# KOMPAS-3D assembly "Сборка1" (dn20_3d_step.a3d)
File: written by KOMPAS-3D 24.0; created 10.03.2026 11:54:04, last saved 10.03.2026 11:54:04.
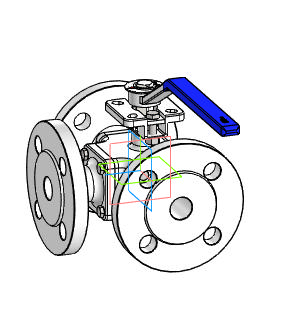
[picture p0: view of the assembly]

Document properties: Автор: R2D2; Полное имя файла: E:\Работа\Зайцев\BV3232P(4pc)-FP-3WL-F-ISO-H Кран шаровой DN.ru Ду15-100 Ру16\DN20\исходные материалы\dn20_3d_step.a3d

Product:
- Component [detail]: Деталь  | qty 1  | Автор: R2D2; source file: Деталь Деталь.m3d
- Component [detail]: Деталь1  | qty 1  | Автор: R2D2; source file: Деталь1 Деталь1.m3d
- Component [detail]: AS 1110 - M6 x 20  | qty 1  | Автор: R2D2; source file: AS 1110 - M6 x 20 AS 1110 - M6 x 20.m3d
- Component [detail]: AS 1110 - M6 x 20  | qty 1  | Комментарий: Болты и винты   шестигранные точные   метрические ISO; Автор: R2D2; additional columns: Сталь, мягкая; source file: AS 1110 - M6 x 20 AS 1110 - M6 x 20.m3d
- Component [detail]: ANSI B18.2.4.2M - M6x1 - 10  | designation ANSI B18.2.4.2M - M6x1  | qty 1  | Автор: R2D2; source file: ANSI B18.2.4.2M - M6x1 ANSI B18.2.4.2M - M6x1 - 10.m3d
- Component [detail]: ANSI B18.2.4.2M - M6x1 - 10  | designation ANSI B18.2.4.2M - M6x1  | qty 1  | Комментарий: Типы метрических   шестигранных гаек   2; Автор: R2D2; additional columns: Сталь, мягкая; source file: ANSI B18.2.4.2M - M6x1 ANSI B18.2.4.2M - M6x1 - 10.m3d
- Component [detail]: AS 1110 - M5 x 10  | qty 1  | Автор: R2D2; source file: AS 1110 - M5 x 10 AS 1110 - M5 x 10.m3d
- Component [detail]: AS 1110 - M5 x 10  | qty 11  | Комментарий: Болты и винты   шестигранные точные   метрические ISO; Автор: R2D2; additional columns: Сталь, мягкая; source file: AS 1110 - M5 x 10 AS 1110 - M5 x 10.m3d
- Part/product: Сборка1

Referenced files in E:\Работа\Зайцев\BV3232P(4pc)-FP-3WL-F-ISO-H Кран шаровой DN.ru Ду15-100 Ру16\DN20\исходные материалы\: Деталь Деталь.m3d, Деталь1 Деталь1.m3d, AS 1110 - M6 x 20 AS 1110 - M6 x 20.m3d, ANSI B18.2.4.2M - M6x1 ANSI B18.2.4.2M - M6x1 - 10.m3d, AS 1110 - M5 x 10 AS 1110 - M5 x 10.m3d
